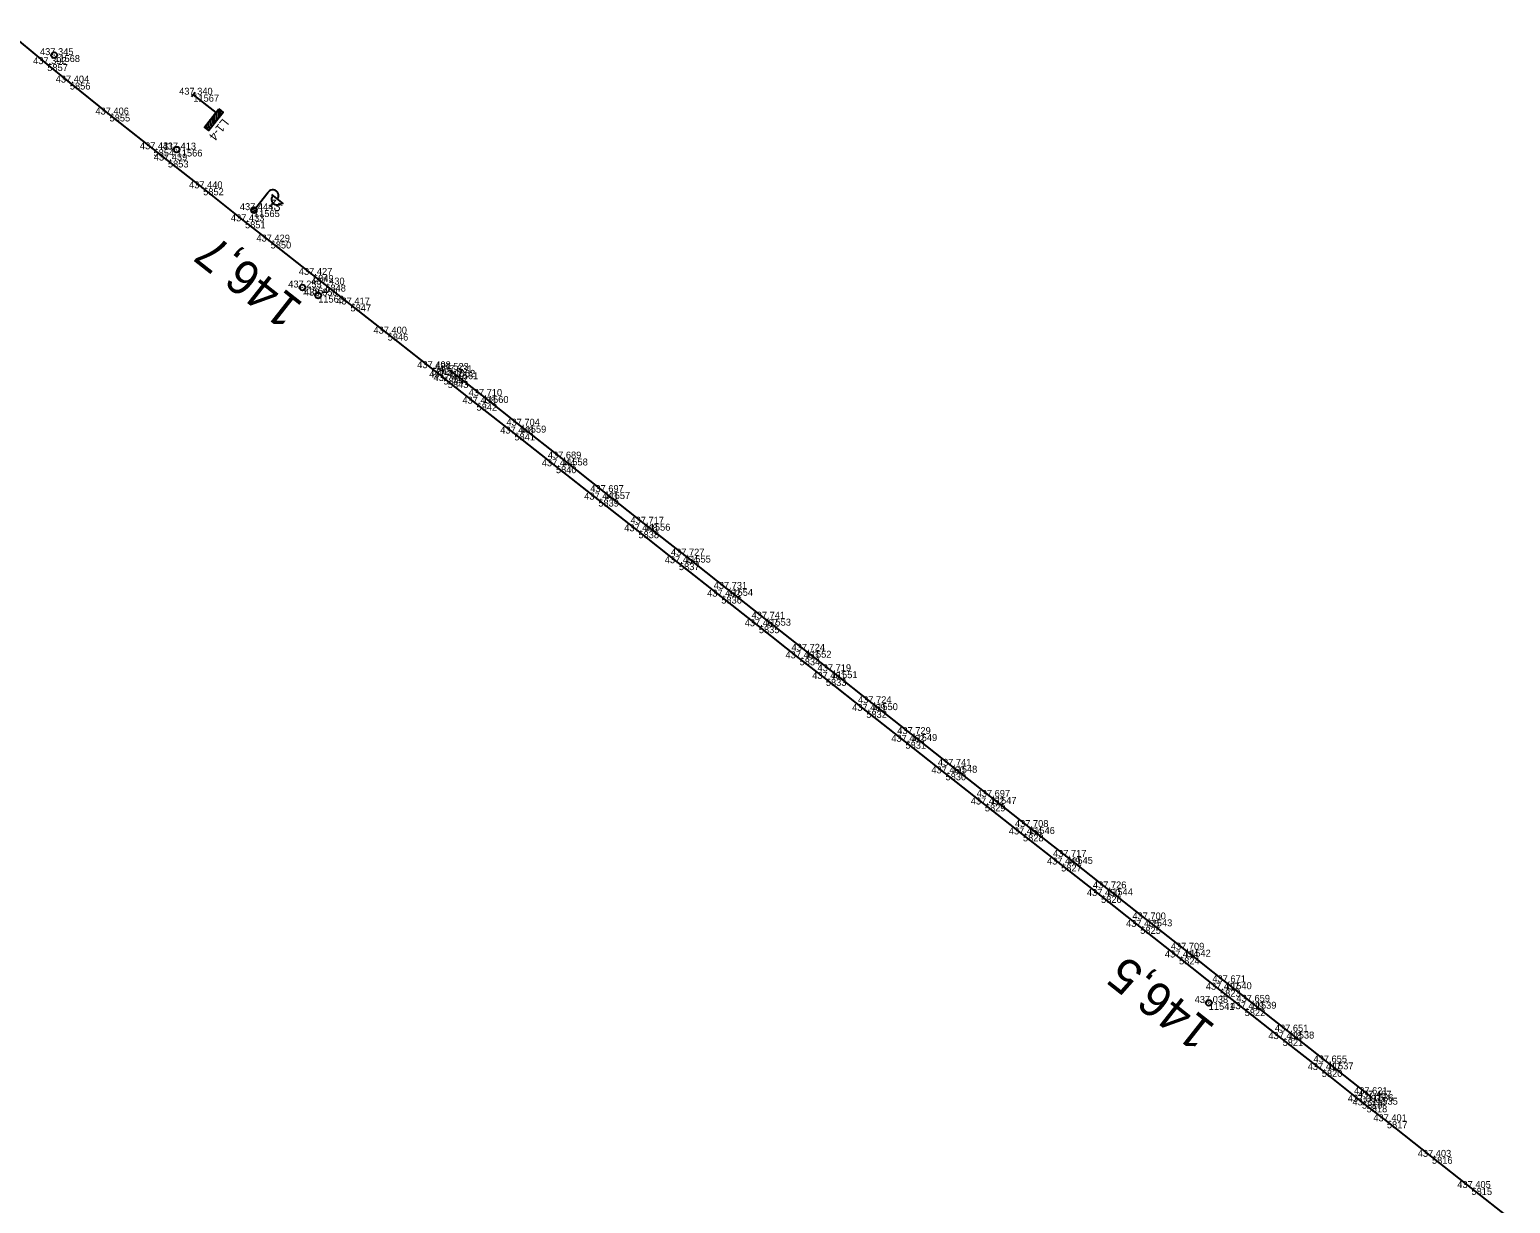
# Model space of a CAD drawing. Extents: x -654154 to -652650, y -1166925 to -1164904.
# Drawn here: x -653396.2 to -653139.6, y -1165912.8 to -1165709.5 of the extents above; entities that cross this region are included whole.
import ezdxf

# ---------------------------------------------------------------- set-up
doc = ezdxf.new("R2010")
doc.units = 0
for name, color, linetype in [('Vrstva 1', 7, 'Continuous'), ('Vrstva 14', 7, 'Continuous'), ('Vrstva 25', 7, 'Continuous'), ('Vrstva 50', 7, 'Continuous'), ('Vrstva 6', 7, 'Continuous'), ('Vrstva 60', 7, 'Continuous'), ('Vrstva 61', 7, 'Continuous'), ('Vrstva 7', 7, 'Continuous')]:
    doc.layers.add(name, color=color, linetype=linetype)

msp = doc.modelspace()

# ---------------------------------------------------------------- linework, layer by layer
at = {"layer": 'Vrstva 1'}
msp.add_lwpolyline([(-653139.57, -1165915.49), (-653146.31, -1165910.17), (-653153.16, -1165904.77), (-653160.97, -1165898.62), (-653164.48, -1165895.86), (-653165.29, -1165895.23), (-653172.25, -1165889.73), (-653179.04, -1165884.38), (-653185.62, -1165879.19), (-653189.89, -1165875.83), (-653196.99, -1165870.24), (-653203.71, -1165864.95), (-653210.5, -1165859.59), (-653217.42, -1165854.14), (-653224.03, -1165848.93), (-653230.63, -1165843.74), (-653237.45, -1165838.35), (-653244.39, -1165832.88), (-653251.18, -1165827.53), (-653258.19, -1165822), (-653262.73, -1165818.43), (-653269.8, -1165812.87), (-653276.31, -1165807.74), (-653283.65, -1165801.95), (-653290.67, -1165796.42), (-653297.62, -1165790.94), (-653304.96, -1165785.16), (-653312.16, -1165779.49), (-653318.72, -1165774.33), (-653323.7, -1165770.4), (-653324.46, -1165769.8), (-653326.53, -1165768.17), (-653334.12, -1165762.19), (-653340.56, -1165757.14), (-653344.93, -1165753.7), (-653347.06, -1165752.02), (-653354.4, -1165746.24), (-653358.84, -1165742.74), (-653366.09, -1165737.02), (-653372.2, -1165732.21), (-653374.69, -1165730.26), (-653382.31, -1165724.24), (-653389.19, -1165718.71), (-653393.1, -1165715.51), (-653400.32, -1165709.54)], dxfattribs=at)
at = {"layer": 'Vrstva 14'}
msp.add_lwpolyline([(-653163.54, -1165894.53), (-653164.29, -1165893.92), (-653171.22, -1165888.42), (-653178.02, -1165883.08), (-653184.57, -1165877.92), (-653188.85, -1165874.54), (-653195.95, -1165868.9), (-653202.62, -1165863.65), (-653209.46, -1165858.28), (-653216.38, -1165852.82), (-653222.97, -1165847.65), (-653229.61, -1165842.43), (-653236.41, -1165837.04), (-653243.36, -1165831.55), (-653250.17, -1165826.2), (-653257.16, -1165820.66), (-653261.68, -1165817.12), (-653268.7, -1165811.57), (-653275.27, -1165806.4), (-653282.58, -1165800.64), (-653289.59, -1165795.11), (-653296.56, -1165789.63), (-653303.9, -1165783.82), (-653311.1, -1165778.14), (-653317.64, -1165772.99), (-653322.88, -1165768.89), (-653323.42, -1165768.47)], dxfattribs=at)
at = {"layer": 'Vrstva 25'}
for p, q in [((-653356.97, -1165740.4), (-653354.81, -1165737.66)), ((-653354.26, -1165738.09), (-653352.21, -1165739.7)), ((-653357.75, -1165740.62), (-653356.88, -1165740.51)), ((-653357.74, -1165740.99), (-653356.79, -1165740.88))]:
    msp.add_line(p, q, dxfattribs=at)
msp.add_circle((-653357.28, -1165740.8), 0.5, dxfattribs=at)
for centre, start, end in [((-653354.02, -1165738.28), 321.7346, 141.7346), ((-653353.24, -1165738.9), 141.032, 322.4371)]:
    msp.add_arc(centre, 1, start, end, dxfattribs=at)
at = {"layer": 'Vrstva 50'}
for p, q in [((-653391.95, -1165713.95), (-653391.85, -1165713.95)), ((-653370.73, -1165730.31), (-653370.63, -1165730.31)), ((-653346.21, -1165755.61), (-653346.11, -1165755.61))]:
    msp.add_line(p, q, dxfattribs=at)
for centre in [(-653391.9, -1165713.95), (-653370.68, -1165730.31), (-653346.16, -1165755.61)]:
    msp.add_circle(centre, 0.5, dxfattribs=at)
at = {"layer": 'Vrstva 6'}
for p, q in [((-653367.49, -1165720.42), (-653368.1, -1165721.2)), ((-653367.8, -1165720.81), (-653363.89, -1165723.9)), ((-653364.32, -1165726.06), (-653364.49, -1165724.65)), ((-653363.99, -1165725.64), (-653364.16, -1165724.24)), ((-653363.67, -1165725.23), (-653363.83, -1165723.82)), ((-653363.34, -1165724.81), (-653363.5, -1165723.41)), ((-653363.01, -1165724.39), (-653363.12, -1165723.49)), ((-653365.37, -1165726.8), (-653365.47, -1165725.9)), ((-653364.98, -1165726.89), (-653365.14, -1165725.49)), ((-653364.65, -1165726.47), (-653364.81, -1165725.07))]:
    msp.add_line(p, q, dxfattribs=at)
msp.add_lwpolyline([(-653363.39, -1165723.27), (-653362.61, -1165723.89), (-653365.09, -1165727.03), (-653365.87, -1165726.41)], close=True, dxfattribs=at)
at = {"layer": 'Vrstva 60'}
for p, q in [((-653391.9, -1165713.95), (-653391.9, -1165713.95)), ((-653393.1, -1165715.51), (-653393.1, -1165715.51)), ((-653389.19, -1165718.71), (-653389.19, -1165718.71)), ((-653367.8, -1165720.81), (-653367.8, -1165720.81)), ((-653382.31, -1165724.24), (-653382.31, -1165724.24)), ((-653374.69, -1165730.26), (-653374.69, -1165730.26)), ((-653372.2, -1165732.21), (-653372.2, -1165732.21)), ((-653370.68, -1165730.31), (-653370.68, -1165730.31)), ((-653366.09, -1165737.02), (-653366.09, -1165737.02)), ((-653358.84, -1165742.74), (-653358.84, -1165742.74)), ((-653357.28, -1165740.8), (-653357.28, -1165740.8)), ((-653354.4, -1165746.24), (-653354.4, -1165746.24)), ((-653347.06, -1165752.02), (-653347.06, -1165752.02)), ((-653348.89, -1165754.2), (-653348.89, -1165754.2)), ((-653346.16, -1165755.61), (-653346.16, -1165755.61)), ((-653344.93, -1165753.7), (-653344.93, -1165753.7)), ((-653340.56, -1165757.14), (-653340.56, -1165757.14)), ((-653334.12, -1165762.19), (-653334.12, -1165762.19)), ((-653326.53, -1165768.17), (-653326.53, -1165768.17)), ((-653323.42, -1165768.47), (-653323.42, -1165768.47)), ((-653324.46, -1165769.8), (-653324.46, -1165769.8)), ((-653323.7, -1165770.4), (-653323.7, -1165770.4)), ((-653322.88, -1165768.89), (-653322.88, -1165768.89)), ((-653317.64, -1165772.99), (-653317.64, -1165772.99)), ((-653318.72, -1165774.33), (-653318.72, -1165774.33)), ((-653311.1, -1165778.14), (-653311.1, -1165778.14)), ((-653312.16, -1165779.49), (-653312.16, -1165779.49)), ((-653303.9, -1165783.82), (-653303.9, -1165783.82)), ((-653304.96, -1165785.16), (-653304.96, -1165785.16)), ((-653297.62, -1165790.94), (-653297.62, -1165790.94)), ((-653296.56, -1165789.63), (-653296.56, -1165789.63)), ((-653290.67, -1165796.42), (-653290.67, -1165796.42)), ((-653289.59, -1165795.11), (-653289.59, -1165795.11)), ((-653282.58, -1165800.64), (-653282.58, -1165800.64)), ((-653283.65, -1165801.95), (-653283.65, -1165801.95)), ((-653275.27, -1165806.4), (-653275.27, -1165806.4)), ((-653276.31, -1165807.74), (-653276.31, -1165807.74)), ((-653268.7, -1165811.57), (-653268.7, -1165811.57)), ((-653269.8, -1165812.87), (-653269.8, -1165812.87)), ((-653261.68, -1165817.12), (-653261.68, -1165817.12)), ((-653262.73, -1165818.43), (-653262.73, -1165818.43)), ((-653258.19, -1165822), (-653258.19, -1165822)), ((-653257.16, -1165820.66), (-653257.16, -1165820.66)), ((-653251.18, -1165827.53), (-653251.18, -1165827.53)), ((-653250.17, -1165826.2), (-653250.17, -1165826.2)), ((-653243.36, -1165831.55), (-653243.36, -1165831.55)), ((-653244.39, -1165832.88), (-653244.39, -1165832.88)), ((-653236.41, -1165837.04), (-653236.41, -1165837.04)), ((-653237.45, -1165838.35), (-653237.45, -1165838.35)), ((-653229.61, -1165842.43), (-653229.61, -1165842.43)), ((-653230.63, -1165843.74), (-653230.63, -1165843.74)), ((-653222.97, -1165847.65), (-653222.97, -1165847.65)), ((-653224.03, -1165848.93), (-653224.03, -1165848.93)), ((-653216.38, -1165852.82), (-653216.38, -1165852.82)), ((-653217.42, -1165854.14), (-653217.42, -1165854.14)), ((-653209.46, -1165858.28), (-653209.46, -1165858.28)), ((-653210.5, -1165859.59), (-653210.5, -1165859.59)), ((-653203.71, -1165864.95), (-653203.71, -1165864.95)), ((-653202.62, -1165863.65), (-653202.62, -1165863.65)), ((-653196.99, -1165870.24), (-653196.99, -1165870.24)), ((-653195.95, -1165868.9), (-653195.95, -1165868.9)), ((-653189.89, -1165875.83), (-653189.89, -1165875.83)), ((-653188.85, -1165874.54), (-653188.85, -1165874.54)), ((-653191.83, -1165878.11), (-653191.83, -1165878.11)), ((-653184.57, -1165877.92), (-653184.57, -1165877.92)), ((-653185.62, -1165879.19), (-653185.62, -1165879.19)), ((-653178.02, -1165883.08), (-653178.02, -1165883.08)), ((-653179.04, -1165884.38), (-653179.04, -1165884.38)), ((-653171.22, -1165888.42), (-653171.22, -1165888.42)), ((-653172.25, -1165889.73), (-653172.25, -1165889.73)), ((-653164.29, -1165893.92), (-653164.29, -1165893.92)), ((-653165.29, -1165895.23), (-653165.29, -1165895.23)), ((-653164.48, -1165895.86), (-653164.48, -1165895.86)), ((-653163.54, -1165894.53), (-653163.54, -1165894.53)), ((-653160.97, -1165898.62), (-653160.97, -1165898.62)), ((-653153.16, -1165904.77), (-653153.16, -1165904.77)), ((-653146.31, -1165910.17), (-653146.31, -1165910.17))]:
    msp.add_line(p, q, dxfattribs=at)
at = {"layer": 'Vrstva 7'}
for p, q in [((-653348.85, -1165754.23), (-653348.93, -1165754.17)), ((-653191.79, -1165878.14), (-653191.87, -1165878.08))]:
    msp.add_line(p, q, dxfattribs=at)
for centre in [(-653348.89, -1165754.2), (-653191.83, -1165878.11)]:
    msp.add_circle(centre, 0.5, dxfattribs=at)

# ---------------------------------------------------------------- texts
at = {"layer": 'Vrstva 25'}
msp.add_text('15', height=1.5, rotation=321.7346, dxfattribs=at).set_placement((-653354.88, -1165739.87))
at = {"layer": 'Vrstva 6'}
msp.add_text('L1-4', height=1.5, rotation=231.6867, dxfattribs=at).set_placement((-653362.69, -1165724.84))
at = {"layer": 'Vrstva 60'}
for s, p in [('11568', (-653391.9, -1165715.15)), ('5857', (-653393.1, -1165716.71)), ('5856', (-653389.19, -1165719.91)), ('11567', (-653367.8, -1165722.01)), ('5855', (-653382.31, -1165725.44)), ('5854', (-653374.69, -1165731.46)), ('5853', (-653372.2, -1165733.41)), ('11566', (-653370.68, -1165731.51)), ('5852', (-653366.09, -1165738.22)), ('5851', (-653358.84, -1165743.94)), ('11565', (-653357.28, -1165742)), ('5850', (-653354.4, -1165747.44)), ('5849', (-653347.06, -1165753.22)), ('11564', (-653348.89, -1165755.4)), ('11563', (-653346.16, -1165756.81)), ('5848', (-653344.93, -1165754.9)), ('5847', (-653340.56, -1165758.34)), ('5846', (-653334.12, -1165763.39)), ('5845', (-653326.53, -1165769.37)), ('11562', (-653323.42, -1165769.67)), ('5844', (-653324.46, -1165771)), ('5843', (-653323.7, -1165771.6)), ('11561', (-653322.88, -1165770.08)), ('11560', (-653317.64, -1165774.19)), ('5842', (-653318.72, -1165775.53)), ('11559', (-653311.1, -1165779.34)), ('5841', (-653312.16, -1165780.69)), ('11558', (-653303.9, -1165785.02)), ('5840', (-653304.96, -1165786.36)), ('5839', (-653297.62, -1165792.14)), ('11557', (-653296.56, -1165790.83)), ('5838', (-653290.67, -1165797.62)), ('11556', (-653289.59, -1165796.31)), ('11555', (-653282.58, -1165801.84)), ('5837', (-653283.65, -1165803.15)), ('11554', (-653275.27, -1165807.6)), ('5836', (-653276.31, -1165808.94)), ('11553', (-653268.7, -1165812.77)), ('5835', (-653269.8, -1165814.07)), ('11552', (-653261.68, -1165818.32)), ('5834', (-653262.73, -1165819.63)), ('5833', (-653258.19, -1165823.2)), ('11551', (-653257.16, -1165821.86)), ('5832', (-653251.18, -1165828.73)), ('11550', (-653250.17, -1165827.4)), ('11549', (-653243.36, -1165832.75)), ('5831', (-653244.39, -1165834.08)), ('11548', (-653236.41, -1165838.24)), ('5830', (-653237.45, -1165839.55)), ('11547', (-653229.61, -1165843.63)), ('5829', (-653230.63, -1165844.94)), ('11546', (-653222.97, -1165848.85)), ('5828', (-653224.03, -1165850.13)), ('11545', (-653216.38, -1165854.02)), ('5827', (-653217.42, -1165855.34)), ('11544', (-653209.46, -1165859.48)), ('5826', (-653210.5, -1165860.79)), ('5825', (-653203.71, -1165866.15)), ('11543', (-653202.62, -1165864.85)), ('5824', (-653196.99, -1165871.44)), ('11542', (-653195.95, -1165870.1)), ('5823', (-653189.89, -1165877.03)), ('11540', (-653188.85, -1165875.74)), ('11541', (-653191.83, -1165879.31)), ('11539', (-653184.57, -1165879.12)), ('5822', (-653185.62, -1165880.39)), ('11538', (-653178.02, -1165884.28)), ('5821', (-653179.04, -1165885.57)), ('11537', (-653171.22, -1165889.62)), ('5820', (-653172.25, -1165890.93)), ('11536', (-653164.29, -1165895.12)), ('5819', (-653165.29, -1165896.43)), ('5818', (-653164.48, -1165897.06)), ('11535', (-653163.54, -1165895.74)), ('5817', (-653160.97, -1165899.82)), ('5816', (-653153.16, -1165905.97)), ('5815', (-653146.31, -1165911.37))]:
    msp.add_text(s, height=1.2, dxfattribs=at).set_placement(p)
at = {"layer": 'Vrstva 61'}
for s, p in [('437.392', (-653395.55, -1165715.51)), ('437.345', (-653394.36, -1165713.95)), ('437.404', (-653391.64, -1165718.71)), ('437.340', (-653370.25, -1165720.81)), ('437.406', (-653384.76, -1165724.24)), ('437.431', (-653377.05, -1165730.26)), ('437.413', (-653373.13, -1165730.31)), ('437.439', (-653374.65, -1165732.21)), ('437.440', (-653368.54, -1165737.02)), ('437.444', (-653359.73, -1165740.8)), ('437.433', (-653361.29, -1165742.74)), ('437.429', (-653356.86, -1165746.24)), ('437.253', (-653351.35, -1165754.2)), ('437.427', (-653349.51, -1165752.02)), ('437.430', (-653347.38, -1165753.7)), ('438.650', (-653348.61, -1165755.61)), ('437.417', (-653343.01, -1165757.14)), ('437.400', (-653336.58, -1165762.19)), ('437.408', (-653328.99, -1165768.17)), ('437.523', (-653325.87, -1165768.47)), ('437.631', (-653325.24, -1165768.89)), ('437.417', (-653326.92, -1165769.8)), ('437.419', (-653326.16, -1165770.4)), ('437.438', (-653321.17, -1165774.33)), ('437.710', (-653320.09, -1165772.99)), ('437.448', (-653314.61, -1165779.49)), ('437.704', (-653313.55, -1165778.14)), ('437.689', (-653306.36, -1165783.82)), ('437.444', (-653307.41, -1165785.16)), ('437.697', (-653299.01, -1165789.63)), ('437.443', (-653300.07, -1165790.94)), ('437.717', (-653292.04, -1165795.11)), ('437.448', (-653293.13, -1165796.42)), ('437.454', (-653286.1, -1165801.95)), ('437.727', (-653285.03, -1165800.64)), ('437.462', (-653278.76, -1165807.74)), ('437.731', (-653277.63, -1165806.4)), ('437.467', (-653272.25, -1165812.87)), ('437.741', (-653271.06, -1165811.57)), ('437.463', (-653265.18, -1165818.43)), ('437.724', (-653264.13, -1165817.12)), ('437.719', (-653259.62, -1165820.66)), ('437.461', (-653260.55, -1165822)), ('437.724', (-653252.62, -1165826.2)), ('437.469', (-653253.63, -1165827.53)), ('437.462', (-653246.84, -1165832.88)), ('437.729', (-653245.81, -1165831.55)), ('437.460', (-653239.9, -1165838.35)), ('437.741', (-653238.77, -1165837.04)), ('437.452', (-653233.07, -1165843.74)), ('437.697', (-653232.06, -1165842.43)), ('437.454', (-653226.48, -1165848.93)), ('437.708', (-653225.42, -1165847.65)), ('437.449', (-653219.87, -1165854.14)), ('437.717', (-653218.83, -1165852.82)), ('437.726', (-653211.91, -1165858.28)), ('437.450', (-653212.95, -1165859.59)), ('437.700', (-653205.07, -1165863.65)), ('437.435', (-653206.17, -1165864.95)), ('437.709', (-653198.41, -1165868.9)), ('437.414', (-653199.44, -1165870.24)), ('437.671', (-653191.21, -1165874.54)), ('437.417', (-653192.34, -1165875.83)), ('437.038', (-653194.28, -1165878.11)), ('437.419', (-653188.08, -1165879.19)), ('437.659', (-653187.03, -1165877.92)), ('437.418', (-653181.5, -1165884.38)), ('437.651', (-653180.38, -1165883.08)), ('437.417', (-653174.7, -1165889.73)), ('437.655', (-653173.68, -1165888.42)), ('437.397', (-653167.74, -1165895.23)), ('437.621', (-653166.65, -1165893.92)), ('437.487', (-653165.99, -1165894.53)), ('437.396', (-653166.93, -1165895.86)), ('437.401', (-653163.32, -1165898.62)), ('437.403', (-653155.62, -1165904.77)), ('437.405', (-653148.77, -1165910.17))]:
    msp.add_text(s, height=1.2, dxfattribs=at).set_placement(p)
at = {"layer": 'Vrstva 7'}
for s, rotation, p in [('146,7', 141.7997, (-653348.54, -1165757.07)), ('146,5', 141.7473, (-653190.46, -1165882.14))]:
    msp.add_text(s, height=6, rotation=rotation, dxfattribs=at).set_placement(p)

doc.saveas('drawing.dxf')
